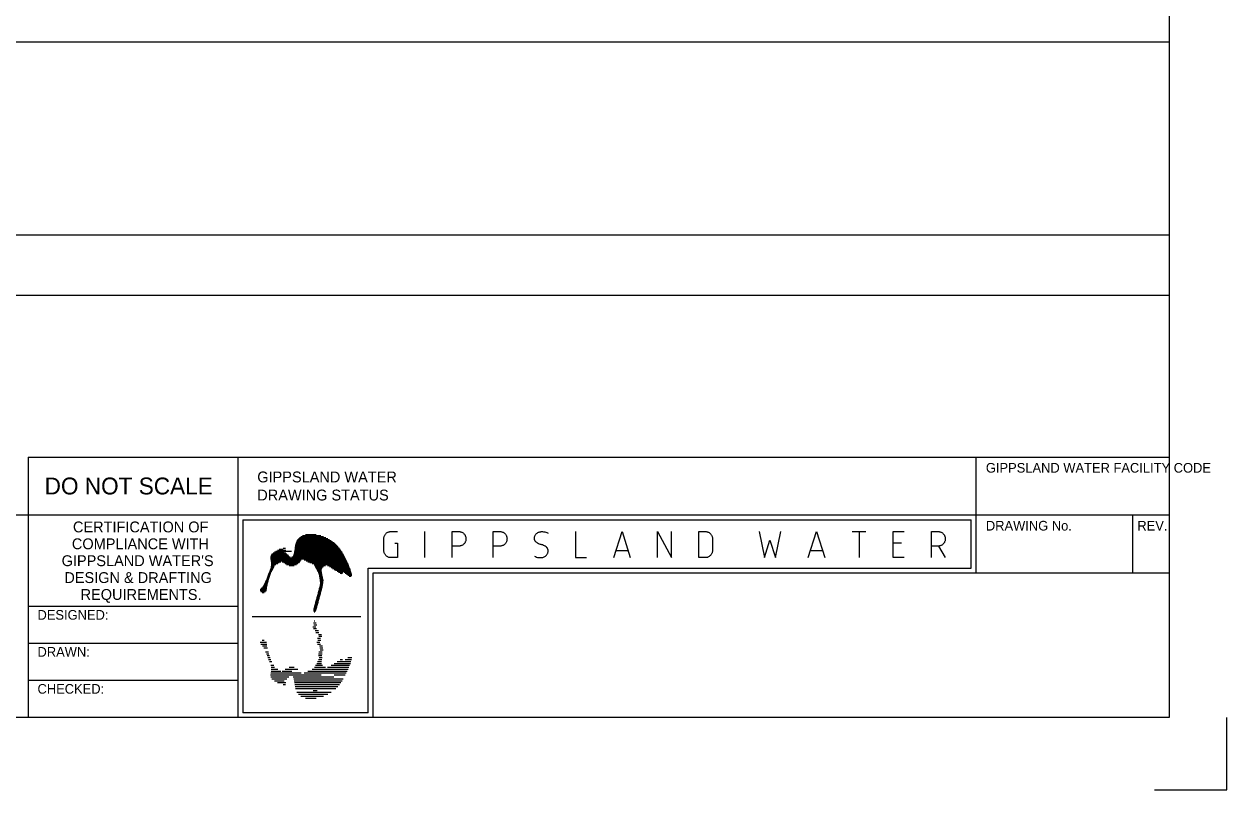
# Model space of a CAD drawing. Extents: x 0 to 841, y 0 to 594.
# Drawn here: x 591.7 to 841, y 0 to 158.8 of the extents above; entities that cross this region are included whole.
import ezdxf

# ---------------------------------------------------------------- set-up
doc = ezdxf.new("R2010")
doc.units = 0
doc.layers.add('A1BORDER', color=7, linetype='Continuous')
doc.layers.add('Level 1', color=7, linetype='Continuous')

msp = doc.modelspace()

# ---------------------------------------------------------------- linework, layer by layer
at = {"layer": 'A1BORDER'}
for p, q in [((829, 581), (829, 15)), ((592.5, 69), (592.5, 15)), ((592.5, 69), (829, 69)), ((636, 69), (636, 15)), ((789, 45), (789, 69)), ((28, 57), (829, 57)), ((637, 56), (788, 56)), ((637, 56), (637, 16)), ((788, 46), (788, 56)), ((821.5, 45), (821.5, 57)), ((649.02, 52.52), (653.76, 52.52)), ((649.39, 52.72), (653.15, 52.72)), ((650.01, 52.92), (652.2, 52.92)), ((644.54, 49.92), (645.36, 49.92)), ((645.37, 50.12), (645.86, 50.12)), ((647.75, 49.92), (657.17, 49.92)), ((647.78, 50.12), (657.02, 50.12)), ((647.81, 50.32), (656.86, 50.32)), ((647.85, 50.52), (656.69, 50.52)), ((647.88, 50.72), (656.5, 50.72)), ((647.91, 50.92), (656.3, 50.92)), ((647.96, 51.12), (656.08, 51.12)), ((648.03, 51.32), (655.85, 51.32)), ((648.12, 51.52), (655.59, 51.52)), ((648.23, 51.72), (655.31, 51.72)), ((648.37, 51.92), (655, 51.92)), ((648.53, 52.12), (654.64, 52.12)), ((648.74, 52.32), (654.24, 52.32)), ((642.73, 48.12), (658.25, 48.12)), ((642.74, 47.92), (658.35, 47.92)), ((642.75, 48.32), (646.79, 48.32)), ((642.79, 47.72), (649.08, 47.72)), ((642.81, 48.52), (646.55, 48.52)), ((642.83, 47.52), (648.95, 47.52)), ((642.9, 48.72), (646.37, 48.72)), ((643.04, 48.92), (646.16, 48.92)), ((643.26, 49.12), (645.9, 49.12)), ((643.54, 49.32), (645.57, 49.32)), ((643.85, 49.52), (647.09, 49.52)), ((644.18, 49.72), (645.89, 49.72)), ((647.19, 48.32), (658.14, 48.32)), ((647.42, 48.52), (658.03, 48.52)), ((647.54, 48.72), (657.92, 48.72)), ((647.61, 48.92), (657.8, 48.92)), ((647.63, 49.12), (657.68, 49.12)), ((647.66, 49.32), (657.57, 49.32)), ((647.69, 49.52), (657.44, 49.52)), ((647.71, 49.72), (657.31, 49.72)), ((649.72, 47.72), (658.45, 47.72)), ((650.12, 47.52), (658.55, 47.52)), ((642.35, 44.92), (642.83, 44.92)), ((642.43, 45.12), (642.9, 45.12)), ((642.5, 45.32), (643, 45.32)), ((642.57, 45.52), (643.1, 45.52)), ((642.65, 45.72), (643.2, 45.72)), ((642.72, 45.92), (643.3, 45.92)), ((642.79, 46.12), (643.4, 46.12)), ((642.84, 46.32), (643.5, 46.32)), ((642.85, 47.31), (644.88, 47.31)), ((642.87, 47.12), (644.57, 47.12)), ((642.87, 46.52), (643.6, 46.52)), ((642.88, 46.92), (644.23, 46.92)), ((642.88, 46.72), (643.83, 46.72)), ((645.14, 47.31), (648.83, 47.31)), ((645.49, 47.12), (648.67, 47.12)), ((645.76, 46.92), (648.42, 46.92)), ((646.05, 46.72), (648.11, 46.72)), ((646.62, 46.52), (647.67, 46.52)), ((650.48, 47.31), (658.64, 47.31)), ((650.87, 47.12), (658.73, 47.12)), ((651.36, 46.92), (658.82, 46.92)), ((651.76, 46.72), (658.9, 46.72)), ((651.88, 46.52), (654.15, 46.52)), ((651.99, 46.32), (653.71, 46.32)), ((652.1, 46.12), (653.52, 46.12)), ((652.2, 45.92), (653.4, 45.92)), ((652.31, 45.72), (653.33, 45.72)), ((652.41, 45.52), (653.31, 45.52)), ((652.5, 45.32), (653.34, 45.32)), ((652.6, 45.12), (653.38, 45.12)), ((652.69, 44.92), (653.41, 44.92)), ((654.57, 46.52), (658.99, 46.52)), ((655, 46.32), (659.07, 46.32)), ((655.31, 46.12), (659.14, 46.12)), ((655.62, 45.92), (659.22, 45.92)), ((655.93, 45.72), (659.29, 45.72)), ((656.24, 45.52), (659.35, 45.52)), ((656.55, 45.32), (659.42, 45.32)), ((656.86, 45.12), (657.74, 45.12)), ((657.17, 44.92), (657.68, 44.92)), ((657.91, 45.12), (659.48, 45.12)), ((658.19, 44.92), (659.54, 44.92)), ((663, 46), (788, 46)), ((663, 16), (663, 46)), ((664, 45), (829, 45)), ((664, 15), (664, 45)), ((641.37, 42.52), (642.09, 42.52)), ((641.46, 42.72), (642.15, 42.72)), ((641.55, 42.92), (642.2, 42.92)), ((641.64, 43.12), (642.25, 43.12)), ((641.73, 43.32), (642.3, 43.32)), ((641.82, 43.51), (642.35, 43.51)), ((641.91, 43.72), (642.41, 43.72)), ((641.99, 43.92), (642.48, 43.92)), ((642.06, 44.12), (642.55, 44.12)), ((642.13, 44.32), (642.62, 44.32)), ((642.21, 44.52), (642.69, 44.52)), ((642.28, 44.72), (642.76, 44.72)), ((652.78, 44.72), (653.44, 44.72)), ((652.83, 44.52), (653.48, 44.52)), ((652.86, 44.32), (653.53, 44.32)), ((652.89, 44.12), (653.57, 44.12)), ((652.91, 43.92), (653.62, 43.92)), ((652.94, 43.72), (653.67, 43.72)), ((652.97, 43.51), (653.71, 43.51)), ((652.99, 42.52), (653.57, 42.52)), ((653, 43.32), (653.69, 43.32)), ((653.02, 43.12), (653.67, 43.12)), ((653.03, 42.72), (653.61, 42.72)), ((653.05, 42.92), (653.64, 42.92)), ((657.51, 44.72), (657.54, 44.72)), ((658.47, 44.72), (659.59, 44.72)), ((658.75, 44.52), (659.58, 44.52)), ((659.02, 44.32), (659.47, 44.32)), ((640.62, 41.32), (641.88, 41.32)), ((640.63, 41.52), (641.93, 41.52)), ((640.72, 41.12), (641.73, 41.12)), ((640.73, 41.72), (641.95, 41.72)), ((640.9, 41.92), (641.97, 41.92)), ((641.03, 40.92), (641.43, 40.92)), ((641.1, 42.12), (642, 42.12)), ((641.25, 42.31), (642.04, 42.31)), ((652.3, 39.92), (652.93, 39.92)), ((652.36, 40.12), (652.99, 40.12)), ((652.41, 40.32), (653.04, 40.32)), ((652.47, 40.52), (653.1, 40.52)), ((652.52, 40.72), (653.15, 40.72)), ((652.57, 40.92), (653.2, 40.92)), ((652.63, 41.12), (653.26, 41.12)), ((652.68, 41.32), (653.31, 41.32)), ((652.74, 41.52), (653.37, 41.52)), ((652.79, 41.72), (653.41, 41.72)), ((652.85, 41.92), (653.45, 41.92)), ((652.9, 42.12), (653.49, 42.12)), ((652.95, 42.31), (653.53, 42.31)), ((636, 38), (592.5, 38)), ((651.65, 37.52), (652.28, 37.52)), ((651.71, 37.72), (652.34, 37.72)), ((651.76, 37.92), (652.39, 37.92)), ((651.82, 38.12), (652.44, 38.12)), ((651.87, 38.32), (652.5, 38.32)), ((651.92, 38.52), (652.55, 38.52)), ((651.98, 38.72), (652.61, 38.72)), ((652.03, 38.92), (652.66, 38.92)), ((652.09, 39.12), (652.72, 39.12)), ((652.14, 39.32), (652.77, 39.32)), ((652.2, 39.52), (652.82, 39.52)), ((652.25, 39.72), (652.88, 39.72)), ((638.93, 35.98), (661.47, 35.98)), ((651.63, 37.32), (652.23, 37.32)), ((651.64, 37.12), (652.17, 37.12)), ((651.79, 36.92), (651.9, 36.92)), ((651.79, 35.04), (651.9, 35.04)), ((651.54, 33.84), (652.17, 33.84)), ((651.63, 34.64), (652.23, 34.64)), ((651.65, 33.44), (652.28, 33.44)), ((651.71, 34.24), (652.34, 34.24)), ((652.03, 33.04), (652.66, 33.04)), ((652.14, 32.64), (652.77, 32.64)), ((636, 30.34), (592.5, 30.34)), ((640.62, 30.64), (641.88, 30.64)), ((640.73, 30.24), (641.95, 30.24)), ((641.03, 31.04), (641.43, 31.04)), ((652.34, 30.64), (652.97, 30.64)), ((652.45, 30.24), (653.07, 30.24)), ((652.47, 31.44), (653.1, 31.44)), ((652.57, 31.04), (653.2, 31.04)), ((652.66, 32.24), (653.29, 32.24)), ((652.77, 31.84), (653.4, 31.84)), ((641.1, 29.84), (642, 29.84)), ((641.37, 29.44), (642.09, 29.44)), ((641.73, 28.64), (642.3, 28.64)), ((641.91, 28.24), (642.41, 28.24)), ((642.06, 27.84), (642.55, 27.84)), ((642.21, 27.44), (642.69, 27.44)), ((652.66, 27.84), (653.35, 27.84)), ((652.72, 28.24), (653.44, 28.24)), ((652.77, 28.64), (653.46, 28.64)), ((652.83, 27.44), (653.48, 27.44)), ((652.9, 29.84), (653.49, 29.84)), ((652.99, 29.44), (653.57, 29.44)), ((653.05, 29.04), (653.64, 29.04)), ((658.75, 27.44), (659.58, 27.44)), ((642.35, 27.04), (642.83, 27.04)), ((642.5, 26.64), (643, 26.64)), ((642.79, 25.84), (643.4, 25.84)), ((642.87, 25.44), (643.6, 25.44)), ((642.88, 25.04), (644.23, 25.04)), ((645.76, 25.04), (648.42, 25.04)), ((646.62, 25.44), (647.67, 25.44)), ((651.36, 25.04), (658.82, 25.04)), ((651.88, 25.44), (654.15, 25.44)), ((652.1, 25.84), (653.52, 25.84)), ((652.31, 26.24), (653.33, 26.24)), ((652.5, 26.64), (653.34, 26.64)), ((652.69, 27.04), (653.41, 27.04)), ((654.57, 25.44), (658.99, 25.44)), ((655.31, 25.84), (659.14, 25.84)), ((655.93, 26.24), (659.29, 26.24)), ((656.55, 26.64), (659.42, 26.64)), ((657.17, 27.04), (657.68, 27.04)), ((658.19, 27.04), (659.54, 27.04)), ((636, 22.67), (592.5, 22.67)), ((642.73, 23.84), (653.27, 23.84)), ((642.79, 24.24), (649.08, 24.24)), ((642.81, 23.44), (646.55, 23.44)), ((642.85, 24.65), (644.88, 24.65)), ((643.04, 23.04), (646.16, 23.04)), ((643.54, 22.64), (645.57, 22.64)), ((645.14, 24.65), (647.18, 24.65)), ((647.42, 23.44), (655.89, 23.44)), ((647.61, 23.04), (657.8, 23.04)), ((647.66, 22.64), (657.57, 22.64)), ((649.72, 24.24), (658.45, 24.24)), ((650.48, 24.65), (658.64, 24.65)), ((655.94, 23.84), (658.25, 23.84)), ((644.18, 22.24), (645.89, 22.24)), ((645.37, 21.84), (645.86, 21.84)), ((647.71, 22.24), (657.31, 22.24)), ((647.78, 21.84), (657.02, 21.84)), ((647.85, 21.44), (656.69, 21.44)), ((647.91, 21.04), (656.3, 21.04)), ((648.23, 20.24), (655.31, 20.24)), ((651.57, 20.64), (652.44, 20.64)), ((648.53, 19.84), (654.64, 19.84)), ((649.02, 19.44), (653.76, 19.44)), ((650.01, 19.04), (652.2, 19.04)), ((829, 15), (28, 15)), ((663, 16), (637, 16)), ((829, 15), (829, 15)), ((841, 0), (841, 15)), ((826, 0), (841, 0))]:
    msp.add_line(p, q, dxfattribs=at)
for points in [[(668.49, 51.15), (669.06, 51.15), (669.06, 48.16), (667.64, 48.16), (667.51, 48.16), (667.39, 48.18), (667.28, 48.21), (667.15, 48.25), (667.04, 48.3), (666.93, 48.36), (666.82, 48.43), (666.73, 48.51), (666.64, 48.6), (666.55, 48.7), (666.48, 48.8), (666.41, 48.91), (666.35, 49.02), (666.31, 49.14), (666.27, 49.27), (666.24, 49.39), (666.22, 49.52), (666.22, 49.66), (666.22, 52.05), (666.22, 52.18), (666.24, 52.31), (666.27, 52.43), (666.31, 52.56), (666.35, 52.67), (666.41, 52.79), (666.48, 52.9), (666.55, 53), (666.64, 53.1), (666.73, 53.19), (666.82, 53.27), (666.93, 53.34), (667.04, 53.4), (667.15, 53.45), (667.28, 53.49), (667.39, 53.52), (667.51, 53.54), (667.64, 53.54), (669.06, 53.54)], [(674.74, 48.16), (674.74, 53.54)], [(680.42, 48.16), (680.42, 53.54), (681.84, 53.54), (681.96, 53.54), (682.08, 53.52), (682.2, 53.49), (682.32, 53.45), (682.43, 53.4), (682.54, 53.34), (682.65, 53.27), (682.74, 53.19), (682.84, 53.1), (682.92, 53), (682.99, 52.9), (683.06, 52.79), (683.12, 52.67), (683.17, 52.56), (683.21, 52.43), (683.23, 52.31), (683.25, 52.18), (683.26, 52.05), (683.25, 51.91), (683.23, 51.78), (683.21, 51.66), (683.17, 51.53), (683.12, 51.42), (683.06, 51.3), (682.99, 51.19), (682.92, 51.09), (682.84, 50.99), (682.74, 50.9), (682.65, 50.82), (682.54, 50.75), (682.43, 50.69), (682.32, 50.64), (682.2, 50.6), (682.08, 50.57), (681.96, 50.55), (681.84, 50.55), (680.42, 50.55)], [(688.93, 48.16), (688.93, 53.54), (690.35, 53.54), (690.47, 53.54), (690.59, 53.52), (690.71, 53.49), (690.83, 53.45), (690.94, 53.4), (691.05, 53.34), (691.16, 53.27), (691.26, 53.19), (691.35, 53.1), (691.43, 53), (691.51, 52.9), (691.57, 52.79), (691.63, 52.67), (691.68, 52.56), (691.72, 52.43), (691.75, 52.31), (691.76, 52.18), (691.77, 52.05), (691.76, 51.91), (691.75, 51.78), (691.72, 51.66), (691.68, 51.53), (691.63, 51.42), (691.57, 51.3), (691.51, 51.19), (691.43, 51.09), (691.35, 50.99), (691.26, 50.9), (691.16, 50.82), (691.05, 50.75), (690.94, 50.69), (690.83, 50.64), (690.71, 50.6), (690.59, 50.57), (690.47, 50.55), (690.35, 50.55), (688.93, 50.55)], [(697.45, 48.46), (697.67, 48.36), (697.9, 48.27), (698.12, 48.21), (698.36, 48.17), (698.6, 48.16), (698.84, 48.16), (698.87, 48.16), (699.03, 48.18), (699.18, 48.21), (699.33, 48.26), (699.48, 48.32), (699.62, 48.4), (699.72, 48.46), (699.81, 48.53), (699.9, 48.61), (699.98, 48.69), (700.05, 48.78), (700.11, 48.88), (700.17, 48.99), (700.22, 49.09), (700.25, 49.21), (700.28, 49.32), (700.29, 49.36), (700.3, 49.44), (700.3, 49.52), (700.3, 49.61), (700.29, 49.69), (700.27, 49.77), (700.25, 49.86), (700.22, 49.93), (700.18, 50.01), (700.14, 50.09), (700.09, 50.15), (700.04, 50.21), (700.01, 50.25), (699.85, 50.39), (699.69, 50.51), (699.52, 50.61), (699.34, 50.7), (699.15, 50.78), (698.95, 50.83), (698.87, 50.85), (698.68, 50.9), (698.49, 50.96), (698.3, 51.04), (698.12, 51.14), (697.96, 51.26), (697.8, 51.39), (697.73, 51.45), (697.67, 51.51), (697.62, 51.57), (697.58, 51.64), (697.53, 51.71), (697.5, 51.79), (697.47, 51.87), (697.46, 51.95), (697.44, 52.04), (697.43, 52.12), (697.43, 52.21), (697.44, 52.29), (697.45, 52.35), (697.47, 52.46), (697.51, 52.58), (697.55, 52.69), (697.61, 52.79), (697.67, 52.89), (697.74, 52.99), (697.82, 53.07), (697.9, 53.15), (697.99, 53.23), (698.02, 53.24), (698.15, 53.33), (698.3, 53.4), (698.44, 53.45), (698.6, 53.5), (698.75, 53.52), (698.87, 53.54), (699.11, 53.55), (699.35, 53.53), (699.58, 53.49), (699.82, 53.43), (700.04, 53.35), (700.27, 53.25)], [(705.96, 53.54), (705.96, 48.16), (708.23, 48.16)], [(713.91, 48.16), (715.61, 53.54), (717.32, 48.16)], [(722.99, 48.16), (722.99, 53.54), (725.83, 48.16), (725.83, 53.54)], [(731.52, 48.16), (731.52, 53.54), (732.94, 53.54), (733.06, 53.54), (733.18, 53.52), (733.3, 53.49), (733.42, 53.45), (733.53, 53.4), (733.64, 53.34), (733.75, 53.27), (733.84, 53.19), (733.94, 53.1), (734.02, 53), (734.09, 52.9), (734.16, 52.79), (734.22, 52.67), (734.27, 52.56), (734.31, 52.43), (734.33, 52.31), (734.35, 52.18), (734.36, 52.05), (734.36, 49.66), (734.35, 49.52), (734.33, 49.39), (734.31, 49.27), (734.27, 49.14), (734.22, 49.02), (734.16, 48.91), (734.09, 48.8), (734.02, 48.7), (733.94, 48.6), (733.84, 48.51), (733.75, 48.43), (733.64, 48.36), (733.53, 48.3), (733.42, 48.25), (733.3, 48.21), (733.18, 48.18), (733.06, 48.16), (732.94, 48.16), (731.52, 48.16)], [(744.01, 53.54), (745.14, 48.16), (746.28, 51.75), (747.41, 48.16), (748.55, 53.54)], [(754.22, 48.16), (755.92, 53.54), (757.63, 48.16)], [(763.31, 53.54), (766.15, 53.54)], [(764.73, 53.54), (764.73, 48.16)], [(774.09, 48.16), (771.82, 48.16), (771.82, 53.54), (774.09, 53.54)], [(779.78, 48.16), (779.78, 53.54), (781.2, 53.54), (781.32, 53.54), (781.44, 53.52), (781.56, 53.49), (781.68, 53.45), (781.79, 53.4), (781.9, 53.34), (782.01, 53.27), (782.1, 53.19), (782.2, 53.1), (782.28, 53), (782.35, 52.9), (782.42, 52.79), (782.48, 52.67), (782.53, 52.56), (782.56, 52.43), (782.59, 52.31), (782.61, 52.18), (782.61, 52.05), (782.61, 51.91), (782.59, 51.78), (782.56, 51.66), (782.53, 51.53), (782.48, 51.42), (782.42, 51.3), (782.35, 51.19), (782.28, 51.09), (782.2, 50.99), (782.1, 50.9), (782.01, 50.82), (781.9, 50.75), (781.79, 50.69), (781.68, 50.64), (781.56, 50.6), (781.44, 50.57), (781.32, 50.55), (781.2, 50.55), (779.78, 50.55)], [(773.53, 51.15), (771.82, 51.15)], [(781.2, 50.55), (782.61, 48.16)], [(714.48, 49.66), (716.75, 49.66)], [(754.79, 49.66), (757.06, 49.66)]]:
    msp.add_lwpolyline(points, dxfattribs=at)
at = {"layer": 'Level 1'}
for p, q in [((829, 155), (28, 155)), ((829, 115), (28, 115)), ((829, 102.5), (28, 102.5))]:
    msp.add_line(p, q, dxfattribs=at)

# ---------------------------------------------------------------- texts
at = {"layer": 'A1BORDER'}
for s, height, p in [('GIPPSLAND WATER FACILITY CODE', 1.99998, (791.03, 65.77)), ('GIPPSLAND WATER', 2.25, (640, 63.75)), ('DO NOT SCALE', 3.5, (595.92188, 61.25)), ('DRAWING STATUS', 2.25, (640, 60)), ('CERTIFICATION OF', 2.25, (601.79483, 53.39)), ('DRAWING No.', 1.99998, (791.03, 53.77)), ('REV.', 1.99998, (822.43, 53.77)), ('COMPLIANCE WITH', 2.25, (601.56974, 49.89)), ("GIPPSLAND WATER'S", 2.25, (599.44633, 46.39)), ('DESIGN & DRAFTING', 2.25, (600.00407, 42.89)), ('REQUIREMENTS.', 2.25, (603.3705, 39.39)), ('DESIGNED:', 1.99998, (594.44, 35.29)), ('DRAWN:', 1.99998, (594.44, 27.62)), ('CHECKED:', 1.99998, (594.44, 19.95))]:
    msp.add_text(s, height=height, dxfattribs=at).set_placement(p)

doc.saveas('drawing.dxf')
